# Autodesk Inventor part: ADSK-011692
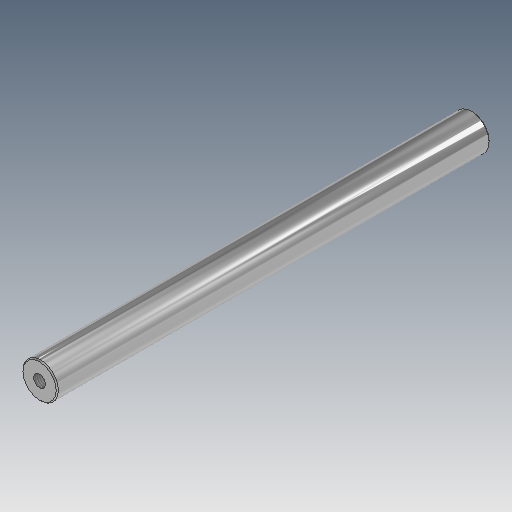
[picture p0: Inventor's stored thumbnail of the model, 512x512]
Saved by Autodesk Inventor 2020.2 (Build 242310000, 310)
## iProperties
Created: 2000-02
Part Number: ADSK-011692
Material: Pearson DGP
Document SubType Name: Modeling
Description: SHFTTA,AX,RG,120,10,EE,GUIDE,OVERHEAD,ADJ
Designer: sspink
Density: 7.83 g/cm^3
Appearance: Chrom - poliert
Mass: 1147.62 g
Surface Area: 263.168 cm^2
Volume: 146.567 cm^3
Control State: 0
Checked Out: False
Master: False
Shininess: 60.0
Length Units: 11269
Angle Units: 11279
Time Units: 11290
Mass Units: 11283
Length Display Precision: 3
Angle Display Precision: 2
Compacted: True
Cutlength: 12.13
Material Desc: ROUND,DGP 1144,1.0000 DIA
Material_Number: A084577
Dimensions: 25x305x25 mm
Mass: 1,148 kg
VLT_Material: Pearson DGP
Density: 7.83
Volumn: 102.96295975261152
Area: 172.2805428931492
PropertySet Name: Model Information
Author: sspink
Revision Number: -
Title: SHFTTA,AX,RG,120,10,EE,GUIDE,OVERHEAD,ADJ
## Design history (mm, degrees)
node "Solide1"
  node "Extrusion1" dims "d1" = 305, "d2" = 0
  node "Hole1" dims "d3" = 8.376, "d4" = 9.525, "d5" = 6.35, "d6" = 60 deg, "d7" = 27.3, "d8" = 118 deg, "d18" = 20
  node "Hole2" dims "d9" = 8.376, "d10" = 9.525, "d11" = 6.35, "d12" = 60 deg, "d13" = 27.3, "d14" = 118 deg, "d19" = 20
  node "Chamfer1" dims "d15" = 0.79375, "d16" = 0.79375, "d17" = 45 deg
sketch "Sketch1"
  geometry: C1 r 12.5 at (0, 0); 1 further point
  constraints: 1 centre point, 1 coincident
  dimensions: "d0" = 25 diameter of C1
node "Corps solides"
node "Corps surfaciques"
sketch "Sketch2"
  geometry: C1 r 12.5 at (0, 0) reference; 1 further point
  constraints: 1 coincident
sketch "Sketch3"
  geometry: C1 r 12.5 at (0, 0) reference; 1 further point
  constraints: 1 coincident
